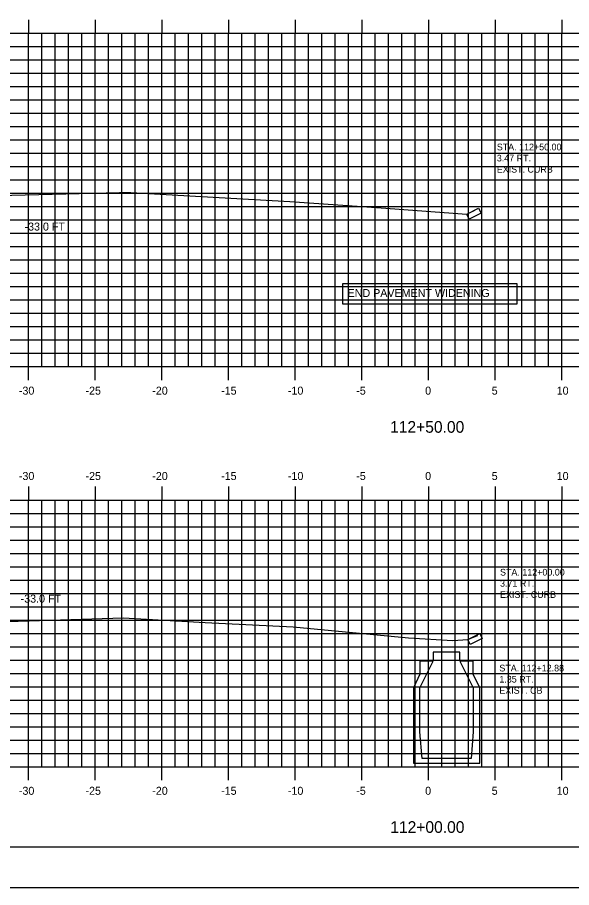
# Model space of a CAD drawing. Extents: x 1668694 to 1668864, y 337823 to 337933.
# Drawn here: x 1668746.7 to 1668788.3, y 337823.4 to 337888.6 of the extents above; entities that cross this region are included whole.
import ezdxf

# ---------------------------------------------------------------- set-up
doc = ezdxf.new("R2010")
doc.units = 0
for name, color, linetype in [('ANNOTATION', 7, 'Continuous'), ('BORDER', 7, 'Continuous'), ('D_Text_Monospaced', 7, 'Continuous'), ('D_Text_Standard', 7, 'Continuous'), ('H_V ANNOTATION', 7, 'Continuous'), ('MAJOR', 7, 'Continuous'), ('MINOR', 7, 'Continuous'), ('PLOT BOUNDARY', 7, 'Continuous'), ('S_Curb_Type_5', 7, 'Continuous'), ('S_Drainage_CB', 7, 'Continuous'), ('S_Roadway_Centerline', 7, 'Continuous')]:
    doc.layers.add(name, color=color, linetype=linetype)

msp = doc.modelspace()

# ---------------------------------------------------------------- linework, layer by layer
at = {"layer": 'ANNOTATION'}
msp.add_lwpolyline([(1668771.123, 337868.679), (1668784.185, 337868.679), (1668784.185, 337867.146), (1668771.123, 337867.146)], close=True, dxfattribs=at)
at = {"layer": 'BORDER'}
msp.add_line((1668702.542, 337826.453), (1668862.542, 337826.453), dxfattribs=at)
at = {"layer": 'MAJOR'}
for p, q in [((1668747.542, 337888.455), (1668747.542, 337887.453)), ((1668752.542, 337888.455), (1668752.542, 337887.453)), ((1668757.542, 337888.455), (1668757.542, 337887.453)), ((1668762.542, 337888.455), (1668762.542, 337887.453)), ((1668767.542, 337888.455), (1668767.542, 337887.453)), ((1668772.542, 337888.455), (1668772.542, 337887.453)), ((1668777.542, 337888.455), (1668777.542, 337887.453)), ((1668782.542, 337888.455), (1668782.542, 337887.453)), ((1668787.542, 337888.455), (1668787.542, 337887.453)), ((1668707.542, 337887.453), (1668847.542, 337887.453)), ((1668707.542, 337887.453), (1668847.542, 337887.453)), ((1668747.542, 337862.453), (1668747.542, 337887.453)), ((1668752.542, 337862.453), (1668752.542, 337887.453)), ((1668757.542, 337862.453), (1668757.542, 337887.453)), ((1668762.542, 337862.453), (1668762.542, 337887.453)), ((1668767.542, 337862.453), (1668767.542, 337887.453)), ((1668772.542, 337862.453), (1668772.542, 337887.453)), ((1668777.542, 337862.453), (1668777.542, 337887.453)), ((1668782.542, 337862.453), (1668782.542, 337887.453)), ((1668787.542, 337862.453), (1668787.542, 337887.453)), ((1668707.542, 337882.453), (1668847.542, 337882.453)), ((1668707.542, 337877.453), (1668847.542, 337877.453)), ((1668707.542, 337872.453), (1668847.542, 337872.453)), ((1668707.542, 337867.453), (1668847.542, 337867.453)), ((1668707.542, 337862.453), (1668847.542, 337862.453)), ((1668707.542, 337862.453), (1668847.542, 337862.453)), ((1668747.542, 337861.451), (1668747.542, 337862.453)), ((1668752.542, 337861.451), (1668752.542, 337862.453)), ((1668757.542, 337861.451), (1668757.542, 337862.453)), ((1668762.542, 337861.451), (1668762.542, 337862.453)), ((1668767.542, 337861.451), (1668767.542, 337862.453)), ((1668772.542, 337861.451), (1668772.542, 337862.453)), ((1668777.542, 337861.451), (1668777.542, 337862.453)), ((1668782.542, 337861.451), (1668782.542, 337862.453)), ((1668787.542, 337861.451), (1668787.542, 337862.453)), ((1668747.542, 337853.455), (1668747.542, 337852.453)), ((1668752.542, 337853.455), (1668752.542, 337852.453)), ((1668757.542, 337853.455), (1668757.542, 337852.453)), ((1668762.542, 337853.455), (1668762.542, 337852.453)), ((1668767.542, 337853.455), (1668767.542, 337852.453)), ((1668772.542, 337853.455), (1668772.542, 337852.453)), ((1668777.542, 337853.455), (1668777.542, 337852.453)), ((1668782.542, 337853.455), (1668782.542, 337852.453)), ((1668787.542, 337853.455), (1668787.542, 337852.453)), ((1668707.542, 337852.453), (1668847.542, 337852.453)), ((1668707.542, 337852.453), (1668847.542, 337852.453)), ((1668747.542, 337832.453), (1668747.542, 337852.453)), ((1668752.542, 337832.453), (1668752.542, 337852.453)), ((1668757.542, 337832.453), (1668757.542, 337852.453)), ((1668762.542, 337832.453), (1668762.542, 337852.453)), ((1668767.542, 337832.453), (1668767.542, 337852.453)), ((1668772.542, 337832.453), (1668772.542, 337852.453)), ((1668777.542, 337832.453), (1668777.542, 337852.453)), ((1668782.542, 337832.453), (1668782.542, 337852.453)), ((1668787.542, 337832.453), (1668787.542, 337852.453)), ((1668707.542, 337847.453), (1668847.542, 337847.453)), ((1668707.542, 337842.453), (1668847.542, 337842.453)), ((1668707.542, 337837.453), (1668847.542, 337837.453)), ((1668707.542, 337832.453), (1668847.542, 337832.453)), ((1668707.542, 337832.453), (1668847.542, 337832.453)), ((1668747.542, 337831.451), (1668747.542, 337832.453)), ((1668752.542, 337831.451), (1668752.542, 337832.453)), ((1668757.542, 337831.451), (1668757.542, 337832.453)), ((1668762.542, 337831.451), (1668762.542, 337832.453)), ((1668767.542, 337831.451), (1668767.542, 337832.453)), ((1668772.542, 337831.451), (1668772.542, 337832.453)), ((1668777.542, 337831.451), (1668777.542, 337832.453)), ((1668782.542, 337831.451), (1668782.542, 337832.453)), ((1668787.542, 337831.451), (1668787.542, 337832.453))]:
    msp.add_line(p, q, dxfattribs=at)
at = {"layer": 'MINOR'}
for p, q in [((1668748.542, 337862.453), (1668748.542, 337887.453)), ((1668749.542, 337862.453), (1668749.542, 337887.453)), ((1668750.542, 337862.453), (1668750.542, 337887.453)), ((1668751.542, 337862.453), (1668751.542, 337887.453)), ((1668753.542, 337862.453), (1668753.542, 337887.453)), ((1668754.542, 337862.453), (1668754.542, 337887.453)), ((1668755.542, 337862.453), (1668755.542, 337887.453)), ((1668756.542, 337862.453), (1668756.542, 337887.453)), ((1668758.542, 337862.453), (1668758.542, 337887.453)), ((1668759.542, 337862.453), (1668759.542, 337887.453)), ((1668760.542, 337862.453), (1668760.542, 337887.453)), ((1668761.542, 337862.453), (1668761.542, 337887.453)), ((1668763.542, 337862.453), (1668763.542, 337887.453)), ((1668764.542, 337862.453), (1668764.542, 337887.453)), ((1668765.542, 337862.453), (1668765.542, 337887.453)), ((1668766.542, 337862.453), (1668766.542, 337887.453)), ((1668768.542, 337862.453), (1668768.542, 337887.453)), ((1668769.542, 337862.453), (1668769.542, 337887.453)), ((1668770.542, 337862.453), (1668770.542, 337887.453)), ((1668771.542, 337862.453), (1668771.542, 337887.453)), ((1668773.542, 337862.453), (1668773.542, 337887.453)), ((1668774.542, 337862.453), (1668774.542, 337887.453)), ((1668775.542, 337862.453), (1668775.542, 337887.453)), ((1668776.542, 337862.453), (1668776.542, 337887.453)), ((1668778.542, 337862.453), (1668778.542, 337887.453)), ((1668779.542, 337862.453), (1668779.542, 337887.453)), ((1668780.542, 337862.453), (1668780.542, 337887.453)), ((1668781.542, 337862.453), (1668781.542, 337887.453)), ((1668783.542, 337862.453), (1668783.542, 337887.453)), ((1668784.542, 337862.453), (1668784.542, 337887.453)), ((1668785.542, 337862.453), (1668785.542, 337887.453)), ((1668786.542, 337862.453), (1668786.542, 337887.453)), ((1668707.542, 337886.453), (1668847.542, 337886.453)), ((1668707.542, 337885.453), (1668847.542, 337885.453)), ((1668707.542, 337884.453), (1668847.542, 337884.453)), ((1668707.542, 337883.453), (1668847.542, 337883.453)), ((1668707.542, 337881.453), (1668847.542, 337881.453)), ((1668707.542, 337880.453), (1668847.542, 337880.453)), ((1668707.542, 337879.453), (1668847.542, 337879.453)), ((1668707.542, 337878.453), (1668847.542, 337878.453)), ((1668707.542, 337876.453), (1668847.542, 337876.453)), ((1668707.542, 337875.453), (1668847.542, 337875.453)), ((1668707.542, 337874.453), (1668847.542, 337874.453)), ((1668707.542, 337873.453), (1668847.542, 337873.453)), ((1668707.542, 337871.453), (1668847.542, 337871.453)), ((1668707.542, 337870.453), (1668847.542, 337870.453)), ((1668707.542, 337869.453), (1668847.542, 337869.453)), ((1668707.542, 337868.453), (1668847.542, 337868.453)), ((1668707.542, 337866.453), (1668847.542, 337866.453)), ((1668707.542, 337865.453), (1668847.542, 337865.453)), ((1668707.542, 337864.453), (1668847.542, 337864.453)), ((1668707.542, 337863.453), (1668847.542, 337863.453)), ((1668748.542, 337832.453), (1668748.542, 337852.453)), ((1668749.542, 337832.453), (1668749.542, 337852.453)), ((1668750.542, 337832.453), (1668750.542, 337852.453)), ((1668751.542, 337832.453), (1668751.542, 337852.453)), ((1668753.542, 337832.453), (1668753.542, 337852.453)), ((1668754.542, 337832.453), (1668754.542, 337852.453)), ((1668755.542, 337832.453), (1668755.542, 337852.453)), ((1668756.542, 337832.453), (1668756.542, 337852.453)), ((1668758.542, 337832.453), (1668758.542, 337852.453)), ((1668759.542, 337832.453), (1668759.542, 337852.453)), ((1668760.542, 337832.453), (1668760.542, 337852.453)), ((1668761.542, 337832.453), (1668761.542, 337852.453)), ((1668763.542, 337832.453), (1668763.542, 337852.453)), ((1668764.542, 337832.453), (1668764.542, 337852.453)), ((1668765.542, 337832.453), (1668765.542, 337852.453)), ((1668766.542, 337832.453), (1668766.542, 337852.453)), ((1668768.542, 337832.453), (1668768.542, 337852.453)), ((1668769.542, 337832.453), (1668769.542, 337852.453)), ((1668770.542, 337832.453), (1668770.542, 337852.453)), ((1668771.542, 337832.453), (1668771.542, 337852.453)), ((1668773.542, 337832.453), (1668773.542, 337852.453)), ((1668774.542, 337832.453), (1668774.542, 337852.453)), ((1668775.542, 337832.453), (1668775.542, 337852.453)), ((1668776.542, 337832.453), (1668776.542, 337852.453)), ((1668778.542, 337832.453), (1668778.542, 337852.453)), ((1668779.542, 337832.453), (1668779.542, 337852.453)), ((1668780.542, 337832.453), (1668780.542, 337852.453)), ((1668781.542, 337832.453), (1668781.542, 337852.453)), ((1668783.542, 337832.453), (1668783.542, 337852.453)), ((1668784.542, 337832.453), (1668784.542, 337852.453)), ((1668785.542, 337832.453), (1668785.542, 337852.453)), ((1668786.542, 337832.453), (1668786.542, 337852.453)), ((1668707.542, 337851.453), (1668847.542, 337851.453)), ((1668707.542, 337850.453), (1668847.542, 337850.453)), ((1668707.542, 337849.453), (1668847.542, 337849.453)), ((1668707.542, 337848.453), (1668847.542, 337848.453)), ((1668707.542, 337846.453), (1668847.542, 337846.453)), ((1668707.542, 337845.453), (1668847.542, 337845.453)), ((1668707.542, 337844.453), (1668847.542, 337844.453)), ((1668707.542, 337843.453), (1668847.542, 337843.453)), ((1668707.542, 337841.453), (1668847.542, 337841.453)), ((1668707.542, 337840.453), (1668847.542, 337840.453)), ((1668707.542, 337839.453), (1668847.542, 337839.453)), ((1668707.542, 337838.453), (1668847.542, 337838.453)), ((1668707.542, 337836.453), (1668847.542, 337836.453)), ((1668707.542, 337835.453), (1668847.542, 337835.453)), ((1668707.542, 337834.453), (1668847.542, 337834.453)), ((1668707.542, 337833.453), (1668847.542, 337833.453))]:
    msp.add_line(p, q, dxfattribs=at)
at = {"layer": 'PLOT BOUNDARY'}
msp.add_lwpolyline([(1668694.449, 337823.394), (1668864.449, 337823.394), (1668864.449, 337933.394), (1668694.449, 337933.394)], close=True, dxfattribs=at)
at = {"layer": 'S_Curb_Type_5'}
for points in [[(1668780.417, 337873.876), (1668781.311, 337874.323), (1668781.497, 337873.951), (1668780.603, 337873.503)], [(1668780.501, 337842.004), (1668781.396, 337842.451), (1668781.582, 337842.078), (1668780.687, 337841.631)]]:
    msp.add_lwpolyline(points, close=True, dxfattribs=at)
at = {"layer": 'S_Drainage_CB'}
for p, q in [((1668777.895, 337840.379), (1668776.91, 337840.379)), ((1668776.91, 337840.379), (1668776.91, 337839.395)), ((1668776.91, 337838.378), (1668777.895, 337840.379)), ((1668780.913, 337840.379), (1668779.896, 337840.379)), ((1668779.896, 337840.379), (1668780.913, 337838.378)), ((1668780.913, 337839.395), (1668780.913, 337840.379)), ((1668776.91, 337839.395), (1668776.418, 337838.378)), ((1668781.405, 337838.378), (1668780.913, 337839.395)), ((1668776.418, 337838.378), (1668776.418, 337832.735)), ((1668776.91, 337835.064), (1668776.91, 337838.378)), ((1668780.913, 337838.378), (1668780.913, 337835.064)), ((1668781.405, 337832.735), (1668781.405, 337838.378)), ((1668777.075, 337833.063), (1668776.91, 337835.064)), ((1668780.913, 337835.064), (1668780.749, 337833.063)), ((1668776.418, 337832.735), (1668781.405, 337832.735)), ((1668780.749, 337833.063), (1668777.075, 337833.063))]:
    msp.add_line(p, q, dxfattribs=at)
msp.add_lwpolyline([(1668780.388, 337840.421), (1668779.896, 337840.421), (1668779.896, 337841.044), (1668777.895, 337841.044), (1668777.895, 337840.421), (1668777.403, 337840.421)], dxfattribs=at)
at = {"layer": 'S_Roadway_Centerline'}
for points in [[(1668707.926, 337877.74), (1668711.458, 337877.552), (1668714.49, 337877.328), (1668721.715, 337874.101), (1668726.556, 337871.915), (1668728.76, 337871.024), (1668729.57, 337870.535), (1668730.921, 337871.165), (1668731.618, 337871.557), (1668737.822, 337873.486), (1668742.511, 337874.996), (1668743.261, 337875.234), (1668754.371, 337875.508), (1668754.902, 337875.52), (1668755.227, 337875.5), (1668767.145, 337874.83), (1668773.992, 337874.351), (1668780.417, 337873.876), (1668780.926, 337874.122), (1668781.008, 337874.174)], [(1668707.542, 337845.711), (1668716.631, 337845.281), (1668718.644, 337844.402), (1668727.452, 337840.436), (1668728.352, 337839.452), (1668729.848, 337838.554), (1668730.966, 337839.591), (1668732.286, 337840.332), (1668739.534, 337842.117), (1668743.45, 337843.271), (1668747.609, 337843.393), (1668754.663, 337843.611), (1668760.806, 337843.271), (1668767.412, 337842.94), (1668776.054, 337842.121), (1668779.365, 337841.912), (1668780.501, 337842.004), (1668780.972, 337842.193), (1668781.252, 337842.292)]]:
    msp.add_lwpolyline(points, dxfattribs=at)

# ---------------------------------------------------------------- texts
at = {"layer": 'ANNOTATION'}
for s, height, p in [('C', 0.0146, (1668767.14, 337874.83)), ('L', 0.0146, (1668767.145, 337874.823)), ('END PAVEMENT WIDENING', 0.6, (1668771.484, 337867.673)), ('C', 0.0146, (1668767.407, 337842.94)), ('L', 0.0146, (1668767.412, 337842.933))]:
    msp.add_text(s, height=height, dxfattribs=at).set_placement(p)
at = {"layer": 'D_Text_Monospaced'}
for s, height, p in [('STA. 112+50.00', 0.49998, (1668782.675, 337878.672)), ('3.47 RT.', 0.5, (1668782.675, 337877.838)), ('EXIST. CURB', 0.49998, (1668782.675, 337876.998)), ('STA. 112+00.00', 0.49998, (1668782.918, 337846.79)), ('3.71 RT.', 0.5, (1668782.918, 337845.956)), ('EXIST. CURB', 0.49998, (1668782.918, 337845.116)), ('STA. 112+12.88', 0.49998, (1668782.867, 337839.601)), ('1.35 RT.', 0.5, (1668782.867, 337838.767)), ('EXIST. CB', 0.5, (1668782.867, 337837.927))]:
    msp.add_text(s, height=height, dxfattribs=at).set_placement(p)
at = {"layer": 'D_Text_Standard'}
for p in [(1668747.253, 337872.653), (1668746.961, 337844.759)]:
    msp.add_text('-33.0 FT', height=0.6, dxfattribs=at).set_placement(p)
at = {"layer": 'H_V ANNOTATION'}
for s, height, p in [('-30', 0.6, (1668746.83, 337860.353)), ('-25', 0.6, (1668751.827, 337860.353)), ('-20', 0.6, (1668756.835, 337860.353)), ('-15', 0.6, (1668761.999, 337860.353)), ('-10', 0.6, (1668767.007, 337860.353)), ('-5', 0.6, (1668772.133, 337860.353)), ('0', 0.6, (1668777.301, 337860.353)), ('5', 0.6, (1668782.293, 337860.353)), ('10', 0.6, (1668787.167, 337860.353)), ('112+50.00', 0.875, (1668774.671, 337857.497)), ('-30', 0.6, (1668746.83, 337853.953)), ('-25', 0.6, (1668751.827, 337853.953)), ('-20', 0.6, (1668756.835, 337853.953)), ('-15', 0.6, (1668761.999, 337853.953)), ('-10', 0.6, (1668767.007, 337853.953)), ('-5', 0.6, (1668772.133, 337853.953)), ('0', 0.6, (1668777.301, 337853.953)), ('5', 0.6, (1668782.293, 337853.953)), ('10', 0.6, (1668787.167, 337853.953)), ('-30', 0.6, (1668746.83, 337830.353)), ('-25', 0.6, (1668751.827, 337830.353)), ('-20', 0.6, (1668756.835, 337830.353)), ('-15', 0.6, (1668761.999, 337830.353)), ('-10', 0.6, (1668767.007, 337830.353)), ('-5', 0.6, (1668772.133, 337830.353)), ('0', 0.6, (1668777.301, 337830.353)), ('5', 0.6, (1668782.293, 337830.353)), ('10', 0.6, (1668787.167, 337830.353)), ('112+00.00', 0.875, (1668774.686, 337827.497))]:
    msp.add_text(s, height=height, dxfattribs=at).set_placement(p)

doc.saveas('drawing.dxf')
